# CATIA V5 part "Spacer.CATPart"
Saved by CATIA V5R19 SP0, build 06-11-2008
Part number: DISTANZIALE
Bounding box of the stored display mesh (mm): x 16.272 to 34.272, y -7.5 to 0.5, z 45.837 to 59.5
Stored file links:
  C:\Users\sisca\Desktop\HELTEC_CASE\Spacer.CATPart
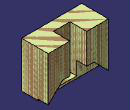
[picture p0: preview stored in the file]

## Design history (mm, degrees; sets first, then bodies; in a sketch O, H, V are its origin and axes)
Set1
  DatumSurface1
  DatumCurve1
  DatumCurve2
  DatumSurface2
  DatumCurve3 to DatumCurve5
  DatumSurface3
  DatumCurve6
  Sketch1 on end face of Pad1, origin (0, 0.5, 0), H (-1, 0, 0), V (0, 0, 1)
    line L1 (-27.7724, 61.5) -> (-22.7724, 61.5)
    line L2 (-22.7724, 61.5) -> (-22.7724, 46.5)
    line L3 (-22.7724, 46.5) -> (-27.7724, 46.5)
    line L4 (-27.7724, 46.5) -> (-27.7724, 61.5)
    reference projected line E1 (-20.5932, 50.5) -> (-30.0008, 50.5) from edge [end face of Pad1 | face of Pocket1 from Sketch3.L2]
    reference projected line E2 (-16.2724, 59.5) -> (-16.2724, 45.8371) from edge [end face of Pad1 | face of Pad1 from Sketch2.L4]
    length L1 = 5
    length L2 = 15
    distance L3 E1 = 4
    distance L2 E2 = 6.5
    horizontal: L1 H, L3 H
    vertical: L2 V, L4 V
  DatumSurface4
  CLDGeom1 "Tessellation.1"
Body1 (main body)
  Sketch2 on face of DatumSurface1, origin (0, -7.5, 0), H (1, 0, 0), V (0, 0, 1)
    line L1 (16.2724, 59.5) -> (34.2724, 59.5)
    line L2 (34.2724, 59.5) -> (34.2724, 45.8371)
    line L3 (34.2724, 45.8371) -> (16.2724, 45.8371)
    line L4 (16.2724, 45.8371) -> (16.2724, 59.5)
    reference projected line E1 (33.7724, 45.8371) -> (16.7724, 45.8371) from edge of DatumCurve1
    reference intersected line E2 (35.2724, 11) -> (35.2724, 61.5) from face of DatumSurface2
    reference projected line E3 (15.2724, 59.5) -> (10, 59.5) from edge of DatumCurve6
    distance L2 L4 = 18
    distance L3 E1 = 0
    distance L2 E2 = 1
    distance E3 L1 = 0
    horizontal: L1 H, L3 H
    vertical: L2 V, L4 V
  Pad1: profile Sketch2, direction (0, 1, 0), length 8
  Sketch3 on end face of Pad1, origin (0, 0.5, 0), H (-1, 0, 0), V (0, 0, 1)
    line L1 (-16.4529, 46.3596) -> (-20.5932, 50.5)
    line L2 (-20.5932, 50.5) -> (-30.0008, 50.5)
    line L3 (-30.0008, 50.5) -> (-34.16, 46.3408)
    line L4 (-34.16, 46.3408) -> (-35.2949, 45.2059)
    point P5 (-35.2949, 45.2059)
    line L5 (-16.4529, 46.3596) -> (-15.2103, 45.1171)
    line L6 (-15.2103, 45.1171) -> (-35.2949, 45.2059)
    point P7 (-35.2949, 45.2059)
    parallelism: L4 L3, L5 L1
    coincidence: P7 L4, L6 P5, P5 P7
  Pocket1: profile Sketch3, direction (0, -1, 0), length 3
  Pocket2: profile Sketch1, direction (0, -1, 0), length 5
